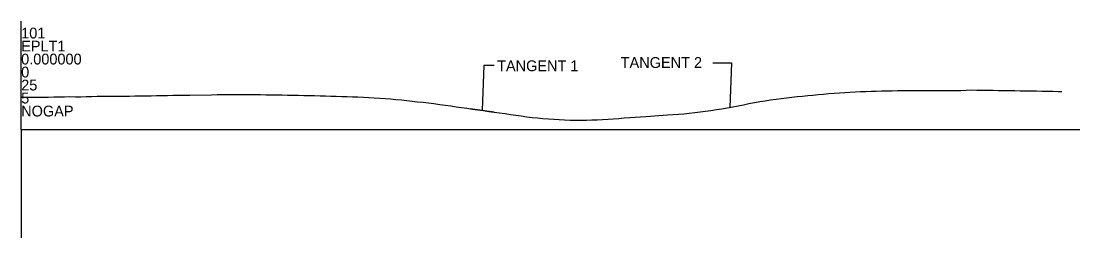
# Model space of a CAD drawing. Extents: x 3880794 to 3915434, y 287517 to 300173.
# Drawn here: x 3910235 to 3915119, y 299173 to 300173 of the extents above; entities that cross this region are included whole.
import ezdxf

# ---------------------------------------------------------------- set-up
doc = ezdxf.new("R2010")
doc.units = 0
for name, color, linetype in [('Level 1', 7, 'Continuous'), ('Level 6', 7, 'Continuous'), ('Level 63', 7, 'Continuous')]:
    doc.layers.add(name, color=color, linetype=linetype)

msp = doc.modelspace()

# ---------------------------------------------------------------- linework, layer by layer
at = {"layer": 'Level 1'}
for points in [[(3912842.4, 299716.3), (3912867.4, 299716.8), (3912892.4, 299717.7), (3912917.4, 299719), (3912942.4, 299720.6), (3912967.4, 299722.3), (3912992.4, 299724.1), (3913017.4, 299725.8), (3913042.4, 299727.6), (3913067.4, 299729.3), (3913092.4, 299731.1), (3913117.4, 299732.8), (3913217.4, 299739.8), (3913242.4, 299741.6), (3913267.4, 299743.5), (3913292.4, 299745.6), (3913317.4, 299748.1), (3913342.4, 299750.8), (3913367.4, 299753.7), (3913392.4, 299757), (3913417.4, 299760.5), (3913442.4, 299764.3), (3913467.4, 299768.3), (3913492.4, 299772.6), (3913517.4, 299777.2), (3913542.4, 299782), (3913567.4, 299787), (3913592.4, 299791.9), (3913617.4, 299796.7), (3913642.4, 299801.3), (3913667.4, 299805.7), (3913692.4, 299809.8), (3913717.5, 299813.3), (3913741.8, 299815.1), (3913766.2, 299818.3), (3913790.5, 299821.4), (3913814.9, 299824.3), (3913839.2, 299827.1), (3913863.6, 299829.5), (3913887.9, 299831.8), (3913912.3, 299833.9), (3913936.6, 299836.1), (3913961, 299838.1), (3913985.3, 299840), (3914009.6, 299841.8), (3914034, 299843.5), (3914058.3, 299844.9), (3914082.7, 299846.3), (3914107, 299847.5), (3914131.3, 299848.5), (3914155.7, 299849.5), (3914180, 299850.2), (3914204.4, 299850.9), (3914228.7, 299851.3), (3914253.1, 299851.7), (3914277.4, 299852), (3914301.7, 299852.3), (3914326.1, 299852.6), (3914350.4, 299852.8), (3914374.8, 299853), (3914399.1, 299853.1), (3914423.5, 299853.2), (3914447.8, 299853.3), (3914472.1, 299853.3), (3914496.5, 299853.3), (3914520.8, 299853.2), (3914545.2, 299853.1), (3914569.5, 299853), (3914593.9, 299854.5), (3914618.7, 299855), (3914643.7, 299854.7), (3914668.7, 299854.4), (3914693.7, 299854.1), (3914718.7, 299853.7), (3914743.7, 299853.3), (3914768.7, 299852.9), (3914793.7, 299852.5), (3914818.7, 299852.1), (3914843.7, 299851.7), (3914868.7, 299851.3), (3914893.7, 299850.9), (3914918.7, 299850.5), (3914943.7, 299850.1), (3914968.7, 299849.6), (3914993.7, 299849.2), (3915018.7, 299848.8), (3915035.4, 299848.6)], [(3910235.4, 299821.6), (3910260.4, 299821.8), (3910285.4, 299821.8), (3910310.4, 299821.9), (3910335.4, 299822.2), (3910360.4, 299822.6), (3910385.4, 299823.1), (3910410.4, 299823.3), (3910435.4, 299823.7), (3910460.4, 299824.2), (3910485.4, 299824), (3910510.4, 299824), (3910535.4, 299824.8), (3910560.4, 299825.5), (3910585.4, 299825.9), (3910610.4, 299826.2), (3910635.4, 299826.5), (3910685.4, 299826.9), (3910710.4, 299826.6), (3910735.4, 299827), (3910760.4, 299827.7), (3910785.4, 299828.1), (3910810.4, 299828.5), (3910835.4, 299828.7), (3910860.4, 299829.3), (3910885.4, 299829.7), (3910910.4, 299830.1), (3910935.4, 299830.7), (3910960.4, 299831.2), (3910985.4, 299831.8), (3911014.1, 299830.8), (3911114.1, 299833.2), (3911139.1, 299833.5), (3911164.1, 299833.7), (3911189.1, 299833.9), (3911214.1, 299834), (3911239.1, 299834.1), (3911264.1, 299834.1), (3911289.1, 299834), (3911314.1, 299833.9), (3911339.1, 299833.7), (3911364.1, 299833.4), (3911389.1, 299833.1), (3911414.1, 299832.7), (3911439.1, 299832.3), (3911464.1, 299831.8), (3911489.1, 299831.3), (3911514.1, 299830.8), (3911539.1, 299830.3), (3911564.1, 299829.7), (3911589.1, 299829), (3911614.1, 299828.4), (3911639.1, 299827.7), (3911664.1, 299826.9), (3911689.1, 299826.2), (3911714.1, 299825.4), (3911739.1, 299824.5), (3911764.1, 299823.6), (3911789.1, 299822.7), (3911814.1, 299821.7), (3911839.1, 299820.4), (3911864.1, 299819), (3911889.1, 299817.4), (3911914.1, 299815.6), (3911939.1, 299813.6), (3911964.1, 299811.4), (3911989.1, 299809), (3912014.1, 299806.4), (3912039.1, 299803.8), (3912064.1, 299801), (3912089.1, 299798.2), (3912114.1, 299795.2), (3912139.1, 299792.2), (3912166.9, 299787.9), (3912191.9, 299784.6), (3912216.9, 299781.3), (3912241.9, 299777.9), (3912266.9, 299774.4), (3912291.9, 299770.8), (3912316.9, 299767.1), (3912341.9, 299763.4), (3912366.9, 299759.8), (3912392, 299756.3), (3912417, 299752.8), (3912442.1, 299749.4), (3912467.2, 299745.9), (3912492.3, 299742.4), (3912517.4, 299739), (3912542.4, 299735.3), (3912567.4, 299731.8), (3912592.4, 299728.7), (3912617.4, 299726), (3912642.4, 299723.5), (3912667.4, 299721.4), (3912692.4, 299719.7), (3912717.4, 299718.3), (3912742.4, 299717.2), (3912767.4, 299716.4), (3912792.4, 299716), (3912817.4, 299716), (3912842.4, 299716.3)]]:
    msp.add_lwpolyline(points, dxfattribs=at)
at = {"layer": 'Level 6'}
msp.add_line((3912306.8, 299769.8), (3912416.8, 299753.7), dxfattribs=at)
for points in [[(3912417.3, 299968.6), (3912369.9, 299968.6), (3912361.8, 299761.7)], [(3913425.5, 299980.5), (3913511.8, 299980.5), (3913504.9, 299774.9)]]:
    msp.add_lwpolyline(points, dxfattribs=at)
at = {"layer": 'Level 63'}
for q in [(3910235.4, 300172.7), (3915118.7, 299672.7), (3910235.4, 299172.7)]:
    msp.add_line((3910235.4, 299672.7), q, dxfattribs=at)

# ---------------------------------------------------------------- texts
at = {"layer": 'Level 6'}
for s, p in [('TANGENT 1', (3912430.8, 299941.6)), ('TANGENT 2', (3913000.9, 299956.8))]:
    msp.add_text(s, height=50, dxfattribs=at).set_placement(p)
at = {"layer": 'Level 63'}
for s, p in [('101', (3910235.4, 300092.7)), ('EPLT1', (3910235.4, 300032.7)), ('0.000000', (3910235.4, 299972.7)), ('0', (3910235.4, 299912.7)), ('25', (3910235.4, 299852.7)), ('5', (3910235.4, 299792.7)), ('NOGAP', (3910235.4, 299732.7))]:
    msp.add_text(s, height=50, dxfattribs=at).set_placement(p)

doc.saveas('drawing.dxf')
